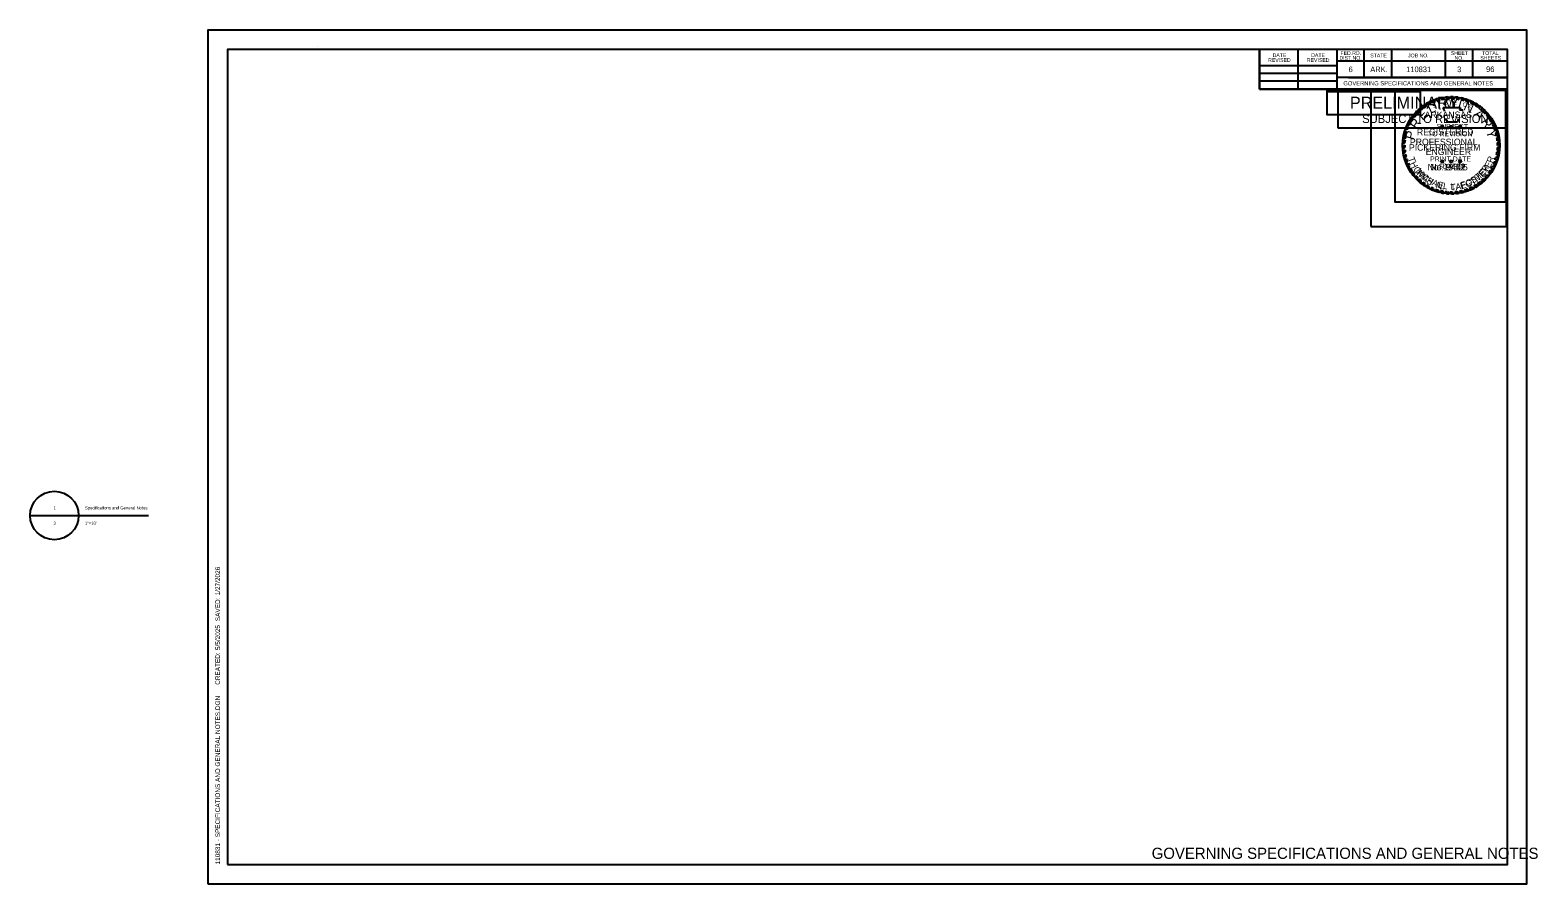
# Model space of a CAD drawing. Extents: x -0.19 to 1.43, y 0 to 0.92.
import ezdxf

# ---------------------------------------------------------------- set-up
doc = ezdxf.new("R2010")
doc.units = 0
for name, color, linetype in [('Default', 7, 'Continuous'), ('DSN_DRFT_Guideline-No-Plot', 7, 'Continuous'), ('SHET_Annotations', 7, 'Continuous'), ('SHET_Border-Lines', 7, 'Continuous'), ('SHET_Border-Text', 7, 'Continuous'), ('SHET_Stamp-Prelim', 7, 'Continuous'), ('SHET_Stamp-Seal', 7, 'Continuous'), ('STAMP_PE DIG SIG', 7, 'Continuous'), ('STAMP_PE_BACKGROUND', 7, 'Continuous'), ('STAMP_PE_FOSTER', 7, 'Continuous'), ('STAMP_PE_SEAL-INFO', 7, 'Continuous'), ('STAMP_PE_TAEGTMEYER', 7, 'Continuous'), ('STAMP_PRELIMINARY', 7, 'Continuous')]:
    doc.layers.add(name, color=color, linetype=linetype)

msp = doc.modelspace()

# ---------------------------------------------------------------- linework, layer by layer
at = {"layer": 'Default'}
for p, q in [((-0.191, 0.3955), (-0.1389, 0.3955)), ((-0.1647, 0.3955), (-0.0639, 0.3955))]:
    msp.add_line(p, q, dxfattribs=at)
msp.add_circle((-0.165, 0.3955), 0.026, dxfattribs=at)
at = {"layer": 'DSN_DRFT_Guideline-No-Plot'}
msp.add_lwpolyline([(0, 0), (1.4167, 0), (1.4167, 0.9167), (0, 0.9167)], close=True, dxfattribs=at)
at = {"layer": 'SHET_Border-Lines'}
for p, q in [((0.1176, 0.8988), (0.1176, 0.8988)), ((0.1176, 0.8988), (0.1176, 0.8988)), ((1.1296, 0.8534), (1.1296, 0.8958)), ((1.1711, 0.8534), (1.1711, 0.8958)), ((1.2127, 0.8958), (1.2127, 0.8534)), ((1.2417, 0.8958), (1.2417, 0.866)), ((1.2712, 0.8958), (1.2712, 0.866)), ((1.3289, 0.8958), (1.3289, 0.866)), ((1.3584, 0.8958), (1.3584, 0.866)), ((1.1296, 0.8786), (1.2127, 0.8786)), ((1.3958, 0.8832), (1.2127, 0.8832)), ((1.3958, 0.8833), (1.3958, 0.8833)), ((1.1296, 0.8706), (1.2127, 0.8706)), ((1.1296, 0.8622), (1.2127, 0.8622)), ((1.3958, 0.866), (1.2127, 0.866)), ((1.2252, 0.866), (1.3958, 0.866)), ((1.3958, 0.8534), (1.1296, 0.8534))]:
    msp.add_line(p, q, dxfattribs=at)
for points in [[(0.0208, 0.0208), (1.3958, 0.0208), (1.3958, 0.8958), (0.0208, 0.8958)], [(1.1296, 0.8534), (1.3958, 0.8534), (1.3958, 0.8958), (1.1296, 0.8958)]]:
    msp.add_lwpolyline(points, close=True, dxfattribs=at)
at = {"layer": 'SHET_Stamp-Prelim'}
msp.add_lwpolyline([(1.2137, 0.8119), (1.3948, 0.8119), (1.3948, 0.8524), (1.2137, 0.8524)], close=True, dxfattribs=at)
at = {"layer": 'SHET_Stamp-Seal'}
msp.add_line((1.3219, 0.7895), (1.3219, 0.7895), dxfattribs=at)
msp.add_lwpolyline([(1.249, 0.7057), (1.3948, 0.7057), (1.3948, 0.8524), (1.249, 0.8524)], close=True, dxfattribs=at)
at = {"layer": 'STAMP_PE DIG SIG'}
msp.add_lwpolyline([(1.2022, 0.8508), (1.3022, 0.8508), (1.3022, 0.8258), (1.2022, 0.8258)], close=True, dxfattribs=at)
at = {"layer": 'STAMP_PE_BACKGROUND'}
for points in [[(1.2022, 0.8517), (1.3022, 0.8517), (1.3022, 0.8258), (1.2022, 0.8258)], [(1.3942, 0.8517), (1.275, 0.8517), (1.275, 0.7325), (1.3942, 0.7325)]]:
    msp.add_lwpolyline(points, close=True, dxfattribs=at)
at = {"layer": 'STAMP_PE_SEAL-INFO'}
for p, q in [((1.3184, 0.8422), (1.3206, 0.8405)), ((1.3217, 0.8432), (1.3233, 0.8413)), ((1.3239, 0.8438), (1.3259, 0.8418)), ((1.3266, 0.8443), (1.3283, 0.8422)), ((1.3295, 0.8447), (1.331, 0.8426)), ((1.3336, 0.8427), (1.3318, 0.8449)), ((1.3364, 0.8428), (1.3348, 0.845)), ((1.3389, 0.8426), (1.3375, 0.845)), ((1.3417, 0.8424), (1.3401, 0.8448)), ((1.3441, 0.842), (1.3427, 0.8445)), ((1.3473, 0.8413), (1.3463, 0.8439)), ((1.3495, 0.8407), (1.3486, 0.8433)), ((1.352, 0.8399), (1.3512, 0.8426)), ((1.2965, 0.8276), (1.2994, 0.8274)), ((1.2983, 0.8295), (1.3014, 0.8293)), ((1.3002, 0.8313), (1.3028, 0.8306)), ((1.3021, 0.833), (1.3051, 0.8325)), ((1.3042, 0.8348), (1.3068, 0.8337)), ((1.3066, 0.8363), (1.309, 0.8352)), ((1.3087, 0.8377), (1.3112, 0.8365)), ((1.3112, 0.8391), (1.3138, 0.8378)), ((1.3137, 0.8403), (1.3158, 0.8387)), ((1.3165, 0.8415), (1.3181, 0.8397)), ((1.3269, 0.8337), (1.3456, 0.8337)), ((1.3276, 0.832), (1.3269, 0.8337)), ((1.3281, 0.8303), (1.3276, 0.832)), ((1.3282, 0.8297), (1.3281, 0.8303)), ((1.3456, 0.8337), (1.3443, 0.831)), ((1.3443, 0.831), (1.3478, 0.831)), ((1.3478, 0.831), (1.347, 0.8297)), ((1.3544, 0.839), (1.3536, 0.8418)), ((1.357, 0.8379), (1.3564, 0.8406)), ((1.3594, 0.8366), (1.359, 0.8394)), ((1.3616, 0.8353), (1.3614, 0.8381)), ((1.364, 0.8337), (1.3639, 0.8366)), ((1.366, 0.8322), (1.3662, 0.8349)), ((1.3685, 0.8301), (1.3687, 0.8331)), ((1.3703, 0.8285), (1.3707, 0.8313)), ((1.3723, 0.8264), (1.3727, 0.8294)), ((1.3738, 0.8247), (1.3746, 0.8273)), ((1.2862, 0.8099), (1.2889, 0.8106)), ((1.287, 0.8121), (1.2898, 0.8129)), ((1.288, 0.8145), (1.2908, 0.8151)), ((1.2891, 0.8167), (1.2918, 0.8171)), ((1.2904, 0.8191), (1.2931, 0.8192)), ((1.2917, 0.8213), (1.2946, 0.8215)), ((1.293, 0.8232), (1.2959, 0.8232)), ((1.2946, 0.8253), (1.2977, 0.8254)), ((1.3252, 0.8129), (1.3241, 0.8137)), ((1.3241, 0.8137), (1.3255, 0.8137)), ((1.3248, 0.8116), (1.3252, 0.8129)), ((1.3259, 0.8124), (1.3248, 0.8116)), ((1.3255, 0.8137), (1.3259, 0.815)), ((1.3259, 0.815), (1.3264, 0.8137)), ((1.327, 0.8116), (1.3259, 0.8124)), ((1.3264, 0.8137), (1.3277, 0.8137)), ((1.3277, 0.8137), (1.3266, 0.8129)), ((1.3266, 0.8129), (1.327, 0.8116)), ((1.3293, 0.8201), (1.3291, 0.8213)), ((1.331, 0.8201), (1.3293, 0.8201)), ((1.331, 0.8177), (1.331, 0.8201)), ((1.3423, 0.8177), (1.331, 0.8177)), ((1.3347, 0.8129), (1.3336, 0.8137)), ((1.3336, 0.8137), (1.335, 0.8137)), ((1.3343, 0.8116), (1.3347, 0.8129)), ((1.3354, 0.8124), (1.3343, 0.8116)), ((1.335, 0.8137), (1.3354, 0.815)), ((1.3354, 0.815), (1.3358, 0.8137)), ((1.3365, 0.8116), (1.3354, 0.8124)), ((1.3358, 0.8137), (1.3372, 0.8137)), ((1.3372, 0.8137), (1.3361, 0.8129)), ((1.3361, 0.8129), (1.3365, 0.8116)), ((1.3424, 0.8196), (1.3423, 0.8177)), ((1.3429, 0.8213), (1.3424, 0.8196)), ((1.3442, 0.8129), (1.3431, 0.8137)), ((1.3431, 0.8137), (1.3445, 0.8137)), ((1.3438, 0.8116), (1.3442, 0.8129)), ((1.3449, 0.8124), (1.3438, 0.8116)), ((1.3445, 0.8137), (1.3449, 0.815)), ((1.3449, 0.815), (1.3453, 0.8137)), ((1.346, 0.8116), (1.3449, 0.8124)), ((1.3453, 0.8137), (1.3467, 0.8137)), ((1.3467, 0.8137), (1.3456, 0.8129)), ((1.3456, 0.8129), (1.346, 0.8116)), ((1.3756, 0.8223), (1.3764, 0.8251)), ((1.3769, 0.8206), (1.3779, 0.8232)), ((1.3786, 0.8178), (1.3796, 0.8205)), ((1.3797, 0.8157), (1.381, 0.8182)), ((1.381, 0.813), (1.3823, 0.8157)), ((1.3818, 0.8112), (1.3832, 0.8136)), ((1.3829, 0.8081), (1.3844, 0.8107)), ((1.2857, 0.796), (1.2834, 0.7946)), ((1.2859, 0.7984), (1.2835, 0.7968)), ((1.2862, 0.8008), (1.2838, 0.7996)), ((1.2867, 0.8034), (1.2841, 0.802)), ((1.2847, 0.8048), (1.2873, 0.8059)), ((1.2853, 0.8071), (1.2879, 0.808)), ((1.3835, 0.8061), (1.3851, 0.8086)), ((1.3842, 0.8029), (1.386, 0.8054)), ((1.3846, 0.8008), (1.3866, 0.8028)), ((1.385, 0.798), (1.387, 0.7998)), ((1.3851, 0.7956), (1.3873, 0.7973)), ((1.3852, 0.7927), (1.3875, 0.7945)), ((1.2856, 0.7933), (1.2834, 0.7914)), ((1.2857, 0.791), (1.2835, 0.7892)), ((1.2858, 0.7882), (1.2838, 0.7862)), ((1.2861, 0.7858), (1.2842, 0.7837)), ((1.2866, 0.7833), (1.2847, 0.7812)), ((1.2871, 0.7809), (1.2854, 0.7786)), ((1.2878, 0.7784), (1.2861, 0.7761)), ((1.3255, 0.7763), (1.3259, 0.7776)), ((1.3259, 0.7776), (1.3264, 0.7763)), ((1.335, 0.7763), (1.3354, 0.7776)), ((1.3354, 0.7776), (1.3358, 0.7763)), ((1.3445, 0.7763), (1.3449, 0.7776)), ((1.3449, 0.7776), (1.3453, 0.7763)), ((1.3827, 0.7774), (1.3855, 0.7785)), ((1.3835, 0.7802), (1.3862, 0.7813)), ((1.3841, 0.7827), (1.3867, 0.7838)), ((1.3846, 0.7855), (1.3871, 0.7867)), ((1.3849, 0.7876), (1.3874, 0.7891)), ((1.3852, 0.7905), (1.3875, 0.792)), ((1.2886, 0.7761), (1.287, 0.7738)), ((1.2895, 0.7737), (1.288, 0.7713)), ((1.2905, 0.7715), (1.2892, 0.769)), ((1.2918, 0.769), (1.2907, 0.7662)), ((1.2931, 0.7667), (1.2921, 0.7641)), ((1.2942, 0.765), (1.2936, 0.7619)), ((1.2958, 0.7628), (1.2952, 0.7598)), ((1.3252, 0.7754), (1.3241, 0.7763)), ((1.3241, 0.7763), (1.3255, 0.7763)), ((1.3248, 0.7741), (1.3252, 0.7754)), ((1.3259, 0.7749), (1.3248, 0.7741)), ((1.327, 0.7741), (1.3259, 0.7749)), ((1.3264, 0.7763), (1.3277, 0.7763)), ((1.3277, 0.7763), (1.3266, 0.7754)), ((1.3266, 0.7754), (1.327, 0.7741)), ((1.3347, 0.7754), (1.3336, 0.7763)), ((1.3336, 0.7763), (1.335, 0.7763)), ((1.3343, 0.7741), (1.3347, 0.7754)), ((1.3354, 0.7749), (1.3343, 0.7741)), ((1.3365, 0.7741), (1.3354, 0.7749)), ((1.3358, 0.7763), (1.3372, 0.7763)), ((1.3372, 0.7763), (1.3361, 0.7754)), ((1.3361, 0.7754), (1.3365, 0.7741)), ((1.3442, 0.7754), (1.3431, 0.7763)), ((1.3431, 0.7763), (1.3445, 0.7763)), ((1.3438, 0.7741), (1.3442, 0.7754)), ((1.3449, 0.7749), (1.3438, 0.7741)), ((1.346, 0.7741), (1.3449, 0.7749)), ((1.3453, 0.7763), (1.3467, 0.7763)), ((1.3467, 0.7763), (1.3456, 0.7754)), ((1.3456, 0.7754), (1.346, 0.7741)), ((1.3738, 0.7612), (1.3763, 0.7608)), ((1.3755, 0.7634), (1.3783, 0.7634)), ((1.3774, 0.7662), (1.3801, 0.7661)), ((1.3783, 0.7677), (1.3811, 0.768)), ((1.3799, 0.7705), (1.3826, 0.7709)), ((1.3808, 0.7724), (1.3835, 0.7729)), ((1.382, 0.7753), (1.3847, 0.776)), ((1.2975, 0.7607), (1.297, 0.7578)), ((1.2992, 0.7588), (1.2988, 0.7559)), ((1.301, 0.757), (1.3008, 0.754)), ((1.3029, 0.7552), (1.3029, 0.7523)), ((1.3049, 0.7536), (1.305, 0.7507)), ((1.3068, 0.7522), (1.307, 0.7493)), ((1.3092, 0.7506), (1.3095, 0.7478)), ((1.3111, 0.7495), (1.3117, 0.7466)), ((1.3138, 0.7481), (1.3147, 0.7452)), ((1.3159, 0.7471), (1.3169, 0.7443)), ((1.3187, 0.7461), (1.3198, 0.7433)), ((1.321, 0.7453), (1.3222, 0.7426)), ((1.3497, 0.7453), (1.352, 0.7436)), ((1.3524, 0.7462), (1.3549, 0.7447)), ((1.3548, 0.7471), (1.3571, 0.7456)), ((1.3573, 0.7483), (1.36, 0.7471)), ((1.3596, 0.7494), (1.3619, 0.7481)), ((1.3619, 0.7508), (1.3644, 0.7497)), ((1.3639, 0.7521), (1.3663, 0.751)), ((1.3664, 0.754), (1.369, 0.7532)), ((1.3679, 0.7553), (1.3706, 0.7545)), ((1.3702, 0.7573), (1.3727, 0.7566)), ((1.3716, 0.7588), (1.3743, 0.7583)), ((1.3238, 0.7445), (1.325, 0.7419)), ((1.326, 0.7441), (1.3274, 0.7415)), ((1.3288, 0.7436), (1.3302, 0.7411)), ((1.3313, 0.7433), (1.3328, 0.7409)), ((1.334, 0.7432), (1.3356, 0.7409)), ((1.3365, 0.7432), (1.3384, 0.741)), ((1.3394, 0.7433), (1.3412, 0.7412)), ((1.3419, 0.7436), (1.344, 0.7416)), ((1.3444, 0.744), (1.3465, 0.7421)), ((1.3471, 0.7446), (1.3492, 0.7427))]:
    msp.add_line(p, q, dxfattribs=at)
for radius, start, end in [(0.0521, 105.2339, 109.0352), (0.0521, 99.7525, 102.7765), (0.0498, 98.258, 101.0329), (0.0521, 93.9381, 96.5517), (0.0498, 92.1102, 95.0367), (0.0521, 87.7298, 90.6707), (0.0498, 85.9628, 88.9097), (0.0521, 81.9732, 84.8236), (0.0498, 79.9264, 82.696), (0.0521, 75.3125, 77.9426), (0.0521, 69.6061, 72.3058), (0.0521, 135.4021, 138.3031), (0.0498, 133.1331, 136.2562), (0.0521, 129.7326, 132.5376), (0.0498, 127.5297, 130.9683), (0.0521, 123.6199, 126.5906), (0.0498, 121.9746, 125.11), (0.0521, 117.6544, 120.8099), (0.0498, 115.6869, 119.1583), (0.0521, 111.3124, 114.7026), (0.0498, 110.3086, 113.1659), (0.0498, 104.0352, 107.3615), (0.0498, 73.5575, 76.2314), (0.0498, 67.6248, 70.504), (0.0521, 63.1329, 66.2704), (0.0498, 61.1558, 64.3784), (0.0521, 56.9003, 60.0942), (0.0498, 54.9238, 58.2702), (0.0498, 48.3016, 52.0395), (0.0521, 50.3492, 53.7159), (0.0498, 42.2212, 45.5512), (0.0521, 44.3405, 47.3929), (0.0521, 38.1247, 41.2316), (0.0521, 158.4077, 161.0701), (0.0521, 152.864, 155.5189), (0.0498, 156.3402, 159.2319), (0.0521, 147.0072, 149.899), (0.0498, 151.0315, 153.573), (0.0521, 141.6056, 144.4486), (0.0498, 145.0197, 148.2104), (0.0498, 139.301, 142.5873), (0.0498, 36.135, 39.5311), (0.0498, 29.9032, 33.6645), (0.0521, 31.9614, 35.4294), (0.0498, 23.7732, 27.2211), (0.0521, 25.9391, 29.0125), (0.0498, 17.6802, 21.4251), (0.0521, 19.9538, 23.3141), (0.0521, 175.7409, 178.2066), (0.0521, 170.0003, 172.6878), (0.0521, 164.3068, 166.894), (0.0498, 173.73, 176.4734), (0.0498, 167.9048, 170.9039), (0.0498, 162.4331, 165.0013), (0.0498, 11.5444, 15.2364), (0.0498, 5.7599, 9.0606), (0.0521, 13.8421, 17.4447), (0.0498, 359.7329, 3.0639), (0.0521, 7.5852, 10.8621), (0.0521, 1.7215, 4.7268), (0.0521, 181.7251, 184.1626), (0.0521, 187.4204, 190.1927), (0.0521, 193.0369, 195.9973), (0.0498, 179.6454, 182.2633), (0.0498, 185.4539, 188.234), (0.0498, 191.2274, 193.9858), (0.0498, 196.9675, 199.8353), (0.0498, 341.777, 345.0925), (0.0498, 348.0778, 351.3435), (0.0498, 353.8632, 357.1274), (0.0521, 343.8925, 347.035), (0.0521, 349.8305, 353.0885), (0.0521, 355.7156, 358.9569), (0.0521, 198.8967, 201.6281), (0.0521, 204.5479, 207.4328), (0.0498, 202.7761, 205.4791), (0.0521, 210.8636, 213.6571), (0.0498, 208.7883, 211.7934), (0.0521, 216.6115, 219.491), (0.0498, 214.1838, 217.2747), (0.0498, 316.6531, 320.3711), (0.0498, 323.5851, 327.4407), (0.0498, 329.5549, 333.2076), (0.0521, 325.4405, 328.9872), (0.0498, 335.6038, 339.1858), (0.0521, 331.4037, 334.9332), (0.0521, 337.3837, 340.9933), (0.0521, 222.48, 225.3801), (0.0498, 220.3909, 223.3056), (0.0521, 228.3665, 231.348), (0.0498, 226.2494, 229.2407), (0.0498, 232.229, 234.9336), (0.0521, 234.295, 236.9452), (0.0498, 238.2223, 240.8353), (0.0521, 240.1977, 242.8613), (0.0498, 244.3204, 246.9486), (0.0521, 246.576, 249.1558), (0.0498, 250.3491, 253.1216), (0.0498, 286.6423, 289.9783), (0.0498, 292.8745, 296.1185), (0.0521, 294.6481, 298.2166), (0.0498, 299.0768, 302.1724), (0.0521, 300.621, 303.8703), (0.0498, 304.823, 308.5143), (0.0521, 306.3721, 310.208), (0.0498, 310.7744, 314.3161), (0.0521, 312.4518, 315.6633), (0.0521, 318.2846, 321.8043), (0.0521, 252.5967, 255.3252), (0.0498, 256.505, 259.1192), (0.0521, 258.4433, 261.1398), (0.0498, 262.3783, 265.2012), (0.0521, 264.1978, 267.1009), (0.0498, 268.3215, 271.277), (0.0521, 270.2548, 273.3361), (0.0498, 274.6157, 277.4486), (0.0521, 276.4239, 279.4357), (0.0498, 280.3459, 283.5814), (0.0521, 282.3199, 285.3702), (0.0521, 288.5709, 291.9733)]:
    msp.add_arc((1.3354, 0.793), radius, start, end, dxfattribs=at)
at = {"layer": 'STAMP_PRELIMINARY'}
msp.add_circle((1.3354, 0.793), 0.0521, dxfattribs=at)

# ---------------------------------------------------------------- texts
at = {"layer": 'Default'}
for s, height, p in [('1', 0.00328, (-0.1658, 0.4021)), ('Specifications and General Notes', 0.003281, (-0.1322, 0.4021)), ('3', 0.00328, (-0.1659, 0.3857)), ('1"=10\'', 0.00328, (-0.1322, 0.3857))]:
    msp.add_text(s, height=height, dxfattribs=at).set_placement(p)
at = {"layer": 'SHET_Annotations'}
for s, height, p in [('6', 0.006, (1.2252, 0.8716)), ('ARK.', 0.006, (1.2485, 0.8716)), ('110831', 0.006, (1.2871, 0.8716)), ('3', 0.006, (1.3418, 0.8716)), ('96', 0.006, (1.3729, 0.8717)), ('GOVERNING SPECIFICATIONS AND GENERAL NOTES', 0.0045, (1.2196, 0.8574)), ('GOVERNING SPECIFICATIONS AND GENERAL NOTES', 0.012, (1.0137, 0.0268))]:
    msp.add_text(s, height=height, dxfattribs=at).set_placement(p)
at = {"layer": 'SHET_Border-Text'}
for s, p in [('DATE', (1.1436, 0.8878)), ('DATE', (1.1851, 0.8878)), ('FED.RD.', (1.2165, 0.8901)), ('STATE', (1.2485, 0.8875)), ('JOB NO.', (1.2891, 0.8875)), ('SHEET', (1.335, 0.8901)), ('TOTAL', (1.3686, 0.8901)), ('REVISED', (1.1388, 0.8826)), ('REVISED', (1.1804, 0.8826)), ('DIST.NO.', (1.2154, 0.8849)), ('NO.', (1.339, 0.8849)), ('SHEETS', (1.3668, 0.8849))]:
    msp.add_text(s, height=0.004, dxfattribs=at).set_placement(p)
for s, p in [('1/27/2026', (0.0129, 0.3097)), ('  SAVED: ', (0.0129, 0.2782)), ('5/5/2025', (0.0129, 0.251)), ('     CREATED: ', (0.0129, 0.2041)), ('110831 - SPECIFICATIONS AND GENERAL NOTES.DGN', (0.0129, 0.0208))]:
    msp.add_text(s, height=0.005, rotation=90, dxfattribs=at).set_placement(p)
at = {"layer": 'SHET_Stamp-Prelim'}
for s, height, p in [('PRELIMINARY', 0.013, (1.2266, 0.8322)), ('SUBJECT TO REVISION', 0.009, (1.2398, 0.817))]:
    msp.add_text(s, height=height, dxfattribs=at).set_placement(p)
at = {"layer": 'STAMP_PE_FOSTER'}
for s, rotation, p in [('M', 308.339, (1.297, 0.7652)), ('I', 314.1842, (1.3014, 0.7599)), ('C', 319.8733, (1.3034, 0.7579)), ('T', 39.4194, (1.3641, 0.7552)), ('E', 46.9613, (1.3689, 0.7594)), ('R', 54.5031, (1.373, 0.764)), ('H', 327.7235, (1.3086, 0.7538)), ('A', 335.7276, (1.3141, 0.7506)), ('E', 343.5779, (1.3204, 0.748)), ('L', 350.8115, (1.3263, 0.7464)), ('L', 1.2666, (1.3349, 0.7455)), ('.', 6.8035, (1.3408, 0.7459)), ('F', 15.8691, (1.3468, 0.7469)), ('O', 23.719, (1.3526, 0.7487)), ('S', 31.7234, (1.3588, 0.7517))]:
    msp.add_text(s, height=0.0067, rotation=rotation, dxfattribs=at).set_placement(p)
msp.add_text('No. 9402', height=0.00698, dxfattribs=at).set_placement((1.313, 0.7661))
at = {"layer": 'STAMP_PE_SEAL-INFO'}
for s, height, p in [('ARKANSAS', 0.00698, (1.3069, 0.8223)), ('REGISTERED', 0.00698, (1.2986, 0.8038)), ('PROFESSIONAL', 0.006983, (1.2911, 0.7932)), ('ENGINEER', 0.00698, (1.3081, 0.7826))]:
    msp.add_text(s, height=height, dxfattribs=at).set_placement(p)
for s, rotation, p in [('S', 23.5541, (1.3164, 0.8327)), ('T', 16.311, (1.3216, 0.8347)), ('A', 9.0679, (1.3269, 0.8361)), ('T', 1.8248, (1.3325, 0.8369)), ('E', 355.2002, (1.3375, 0.8369)), ('O', 342.2506, (1.3472, 0.8354)), ('F', 335.0075, (1.3526, 0.8335))]:
    msp.add_text(s, height=0.00436, rotation=rotation, dxfattribs=at).set_placement(p)
at = {"layer": 'STAMP_PE_TAEGTMEYER'}
for s, rotation, p in [('T', 289.646, (1.289, 0.7791)), ('R', 69.57, (1.3798, 0.7735)), ('H', 296.7339, (1.291, 0.7736)), ('O', 303.7708, (1.2943, 0.7674)), ('M', 314.2033, (1.298, 0.7621)), ('M', 39.3, (1.3633, 0.7533)), ('E', 46.8094, (1.3692, 0.7582)), ('Y', 53.9986, (1.3733, 0.7628)), ('E', 63.0984, (1.377, 0.768)), ('A', 321.0594, (1.3034, 0.7567)), ('S', 327.8239, (1.308, 0.7531)), ('N', 344.2727, (1.3186, 0.7474)), ('.', 350.6464, (1.3254, 0.7456)), ('T', 3.0061, (1.3347, 0.7445)), ('A', 8.9826, (1.3405, 0.7448)), ('E', 17.6836, (1.3463, 0.7457)), ('G', 23.3052, (1.3522, 0.7475)), ('T', 31.466, (1.3583, 0.7503))]:
    msp.add_text(s, height=0.00698, rotation=rotation, dxfattribs=at).set_placement(p)
msp.add_text('No. 19605', height=0.00698, dxfattribs=at).set_placement((1.3101, 0.7661))
at = {"layer": 'STAMP_PRELIMINARY'}
for s, rotation, p in [('M', 3.1074, (1.3278, 0.8326)), ('I', 342.3164, (1.3416, 0.833)), ('E', 42.3578, (1.3048, 0.8192)), ('L', 25.513, (1.3131, 0.8266)), ('I', 12.5248, (1.3217, 0.8309)), ('N', 333.9382, (1.3478, 0.8315)), ('A', 315.6579, (1.3591, 0.8257)), ('R', 56.2292, (1.2984, 0.8095)), ('R', 301.3831, (1.3668, 0.8184)), ('Y', 283.2593, (1.3729, 0.8084)), ('P', 73.913, (1.2953, 0.7982))]:
    msp.add_text(s, height=0.0101, rotation=rotation, dxfattribs=at).set_placement(p)
for s, height, p in [('SUBJECT', 0.00536, (1.3198, 0.8106)), ('PICKERING FIRM', 0.006983, (1.29, 0.7872)), ('TO REVISION', 0.005363, (1.3105, 0.8028)), ('PRINT DATE', 0.00536, (1.3128, 0.7757)), ('$DATE$', 0.00536, (1.3222, 0.768))]:
    msp.add_text(s, height=height, dxfattribs=at).set_placement(p)

doc.saveas('drawing.dxf')
